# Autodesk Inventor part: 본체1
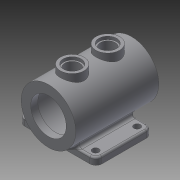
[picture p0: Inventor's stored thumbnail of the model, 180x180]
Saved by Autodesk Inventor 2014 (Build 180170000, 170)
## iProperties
Created: 2014-12
Part Number: 본체1
Material: 일반
Document SubType Name: Modeling
Designer: Owner
Density: 1 g/cm^3
Appearance: 기본값
Author: Owner
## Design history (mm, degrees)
sketch "스케치1"
  geometry: L1 (-70, 0)-(70, 0); L2 (-70, 30)-(-70, 46); L3 (-70, 46)-(70, 46); L4 (70, 46)-(70, 30); L5 (-58, 30)-(-58, 37.5); L6 (-58, 37.5)-(58, 37.5); L7 (58, 37.5)-(58, 30); L8 (-70, 30)-(-58, 30); L9 (58, 30)-(70, 30); 3 further points
  constraints: 18 end point, 9 perpendicular, 3 equal length, 2 midpoint, 1 coincident, 1 horizontal, 1 parallel, 1 vertical alignment
  dimensions: "d0" = 140 distance of L1.end L1.start; "d2" = 92 diameter of L3 L1; "d3" = 75 diameter of L6 L1; "d4" = 60 diameter of L8 L1; "d5" = 12 distance of L2.start L5.start
revolve "회전1" sketch "스케치1" stored, may be unused: angle "d6" = 90 deg
node "작업 평면1"
sketch "스케치3"
  geometry: L1 (0, 0)-(0, -50); L2 (-65, -50)-(65, -50); L3 (-65, -50)-(-65, -38); L4 (-65, -38)-(65, -38); L5 (65, -38)-(65, -50); C1 r 46 at (0, 0) reference; 2 further points
  constraints: 10 end point, 4 perpendicular, 3 coincident, 1 midpoint, 1 vertical
  dimensions: "d8" = 50 distance of L1.start L1.end; "d9" = 130 distance of L2.start L2.end; "d10" = 12 distance of L2.start L3.end
extrude "돌출1" join sketch "스케치3" distance "d11" = 95; taper "d12" = 0 deg
node "작업 평면2"
sketch "스케치5"
  geometry: L1 (46, -70)-(-46, -70) reference; L2 (46, 70)-(-46, 70) reference; C1 r 20 at (0, -30); C2 r 20 at (0, 30); 1 further point
  constraints: 2 centre point, 2 vertical alignment
  dimensions: "d14" = 40 diameter of C1; "d15" = 40 diameter of C2; "d16" = 40 distance from line of L1 C1.centre; "d17" = 40 distance from line of L2 C2.centre
extrude "돌출2" join sketch "스케치5" stored distance "d18" = 95; taper "d19" = 0 deg
sketch "스케치6"
  geometry: C1 r 20 at (0, 0) reference; C2 r 15 at (0, 0); 1 further point
  constraints: 1 centre point, 1 coincident
  dimensions: "d20" = 30 diameter of C2
extrude "돌출3" cut sketch "스케치6" distance "d21" = 5; taper "d22" = 0 deg
sketch "스케치7"
  geometry: C1 r 20 at (0, 0) reference; C2 r 15 at (0, 0); 1 further point
  constraints: 1 centre point, 1 coincident
  dimensions: "d23" = 30 diameter of C2
extrude "돌출4" cut sketch "스케치7" distance "d24" = 5; taper "d25" = 0 deg
sketch "스케치8"
  geometry: C1 r 15 at (0, 0) reference; C2 r 12.5 at (0, 0); 1 further point
  constraints: 1 centre point, 1 coincident
  dimensions: "d26" = 25 diameter of C2
extrude "돌출5" cut sketch "스케치8" stored distance "d27" = 5; taper "d28" = 0 deg
sketch "스케치9"
  geometry: C1 r 15 at (0, 0) reference; C2 r 12.5 at (0, 0); 1 further point
  constraints: 1 centre point, 1 coincident
  dimensions: "d29" = 25 diameter of C2
extrude "돌출6" cut sketch "스케치9" stored distance "d30" = 5; taper "d31" = 0 deg
fillet "모깎기1" dims "d32" = 10
sketch "스케치13"
  geometry: L1 (110, 0)-(0, 0) reference; L2 (120, 10)-(120, 85) reference; L3 (-10, 10)-(-10, 85) reference; L4 (101, -15)-(9, -15) reference; L5 (101, 125)-(9, 125) reference; L6 (29.077, 95)-(80.923, 95) reference; L7 (80.923, 95)-(80.923, 0) reference; L8 (80.923, 0)-(29.077, 0) reference; L9 (29.077, 0)-(29.077, 95) reference; L10 (55, 125)-(55, -15); C1 r 5.5 at (107, 12.5); C2 r 5.5 at (3, 12.5); 3 further points
  constraints: 2 centre point, 2 end point, 2 midpoint, 2 other
  dimensions: "d53" = 12.5 distance from line of L1 C1.centre; "d54" = 11 diameter of C1; "d59" = 13 distance from line of L2 C1.centre; "d60" = 11 diameter of C2; "d61" = 12.5 distance from line of L1 C2.centre; "d62" = 13 distance from line of L3 C2.centre
extrude "돌출8" cut sketch "스케치13" stored distance "d63" = 5; taper "d64" = 0 deg
sketch "스케치14"
  geometry: L1 (120, 10)-(120, 85) reference; L2 (0, 95)-(110, 95) reference; L3 (-10, 10)-(-10, 85) reference; C1 r 5.5 at (107, 82.5); C2 r 5.5 at (3, 82.5); 1 further point
  constraints: 2 centre point
  dimensions: "d74" = 13 distance from line of L1 C1.centre; "d75" = 12.5 distance from line of L2 C1.centre; "d76" = 13 distance from line of L3 C2.centre; "d77" = 12.5 distance from line of L2 C2.centre; "d78" = 11 diameter of C2; "d79" = 11 diameter of C1
extrude "돌출9" cut sketch "스케치14" stored distance "d80" = 5; taper "d81" = 0 deg
sketch "스케치15"
  geometry: L1 (-39.077, 10)-(-39.077, 85) reference; C1 r 5.5 at (-26.077, 82.5) reference; 2 further points
  constraints: 1 other
  dimensions: "d82" = 35 vertical distance of C1.centre point (-31.077, 47.5); "d83" = 8 distance from line of L1 point (-31.077, 47.5)
feature "엠보싱1" sketch "스케치15" dims "d0" = 140, "d2" = 92, "d3" = 75, "d4" = 60, "d5" = 12, "d84" = 1, "d85" = 0
fillet "모깎기2" dims "d86" = 3
fillet "모깎기3" dims "d87" = 5
node "솔리드1"
node "투영된 루프1"
other parameters: "d7" = -15, "d13" = 56
